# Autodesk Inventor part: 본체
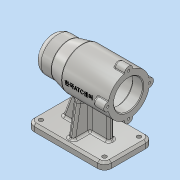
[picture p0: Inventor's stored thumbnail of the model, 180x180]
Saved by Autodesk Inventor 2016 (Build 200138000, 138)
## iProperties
Created: 2019-07
Part Number: 본체
Material: 알루미늄 6061
Document SubType Name: Modeling
Designer: Administrator
Mass: 644.223 g
Surface Area: 653.912 cm^2
Volume: 238.601 cm^3
Density: 2.7 g/cm^3
Appearance: 알루미늄 - 평지
Author: Administrator
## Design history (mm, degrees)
sketch "스케치1"
  geometry: L1 (0, 0)-(30, 0); L2 (30, 0)-(30, 66.631); L3 (29.91, 67.358)-(25.09, 86.642); L4 (25, 87.369)-(25, 102); L5 (15, 112)-(0, 112); L6 (0, 112)-(0, 0); L7 (21, 0)-(21, 15); L8 (21, 15)-(21, 15); L9 (24, 18)-(24, 66); L10 (21, 69)-(21, 69); L11 (21, 69)-(21, 80.7); L12 (20.7, 81)-(17.5, 81); L13 (17.5, 81)-(17.5, 98.7); L14 (17.2, 99)-(16, 99); L15 (16, 99)-(16, 102.7); L16 (15.7, 103)-(10.5, 103); L17 (10.5, 103)-(10.5, 103); L18 (7.5, 106)-(0, 106); A1 r 0.3 centre (15.7, 102.7) between (16, 102.7) and (15.7, 103); A2 r 0.3 centre (17.2, 98.7) between (17.5, 98.7) and (17.2, 99); A3 r 0.3 centre (20.7, 80.7) between (21, 80.7) and (20.7, 81); A4 r 10 centre (15, 102) between (25, 102) and (15, 112); A5 r 3 centre (28, 87.369) between (25, 87.369) and (25.09, 86.642); A6 r 3 centre (27, 66.631) between (30, 66.631) and (29.91, 67.358); A7 r 3 centre (21, 66) between (24, 66) and (21, 69); A8 r 3 centre (21, 18) between (21, 15) and (24, 18); A9 r 3 centre (7.5, 103) between (10.5, 103) and (7.5, 106); 3 further points
  constraints: 36 end point, 18 point on circle, 18 tangent, 14 perpendicular, 9 centre point, 8 point on line, 5 equal radius, 2 horizontal, 1 parallel
  dimensions: "d0" = 112 distance between parallel lines of L1 L5; "d1" = 60 diameter of L2 L6; "d2" = 50 diameter of L4 L6; "d3" = 25 distance of point (25, 87) point (25, 112); "d4" = 45 distance from line of point (30, 67) L5; "d5" = 42 diameter of L7 L6; "d6" = 48 diameter of L9 L6; "d7" = 42 diameter of L11 L6; "d8" = 35 diameter of L13 L6; "d9" = 32 diameter of L15 L6; "d10" = 21 diameter of L17 L6; "d11" = 3 distance between parallel lines of L16 L18; "d12" = 4 distance between parallel lines of L14 L16; "d13" = 18 distance between parallel lines of L12 L14; "d14" = 12 distance between parallel lines of L10 L12; "d15" = 54 distance between parallel lines of L8 L10; "d16" = 15 distance between parallel lines of L1 L8; "d17" = 0.3 radius of A1; "d18" = 10 radius of A4; "d19" = 3 radius of A5; "d20" = 3 radius of A7
revolve "회전1" sketch "스케치1" stored, may be unused: angle "d21" = 90 deg
node "작업 평면1"
sketch "스케치2"
  geometry: L1 (25, 112)-(-25, 112); L2 (-35, 102)-(-35, 10); L3 (-25, 0)-(25, 0); L4 (35, 10)-(35, 102); L5 (-30, 0)-(30, 0) reference; A1 r 10 centre (25, 102) between (35, 102) and (25, 112); A2 r 10 centre (-25, 102) between (-25, 112) and (-35, 102); A3 r 10 centre (-25, 10) between (-35, 10) and (-25, 0); A4 r 10 centre (25, 10) between (25, 0) and (35, 10); 1 further point
  constraints: 8 end point, 8 point on circle, 8 tangent, 4 centre point, 3 equal radius, 2 parallel, 1 collinear, 1 horizontal, 1 perpendicular
  dimensions: "d23" = 112 distance between parallel lines of L3 L1; "d24" = 70 distance between parallel lines of L2 L4; "d25" = 35 distance from line of point (0, 0) L4; "d26" = 10 radius of A1
extrude "돌출1" join sketch "스케치2" distance "d27" = 10; taper "d28" = 0 deg
hole "구멍1" diameter "d31" = 6; stored, may be unused: countersink angle "d35" = 90 deg, drill point angle "d37" = 118 deg; dims "d29" = 10, "d30" = 10, "d32" = 6, "d33" = 4, "d34" = 2, "d36" = 8
node "작업 평면2"
sketch "스케치3"
  geometry: L1 (-25, -70)-(-35, -70) reference; L2 (-28, -70)-(-21.176, -31.302); L3 (35, -70)-(25, -70) reference; L4 (28, -70)-(21.619, -33.809); L5 (-35, -80)-(-35, -70) reference; L6 (35, -80)-(35, -70) reference; 1 further point
  constraints: 4 end point, 2 point on line
  dimensions: "d45" = 7 distance from line of L2.start L5; "d46" = 7 distance from line of L6 L4.start; "d47" = 100 deg angle of L1 L2; "d48" = 100 deg angle of L3 L4
sketch "스케치4"
  geometry: L1 (-4, -60)-(4, -60); L2 (4, -60)-(4, -25); L3 (4, -25)-(-4, -25); L4 (-4, -25)-(-4, -60); L5 (-25, 0)-(25, 0) reference; 1 further point
  constraints: 8 end point, 2 parallel, 1 horizontal, 1 perpendicular
  dimensions: "d49" = 8 distance between parallel lines of L4 L2; "d50" = 4 distance from line of point (0, 0) L4; "d51" = 25 distance between parallel lines of L5 L3; "d52" = 60 distance between parallel lines of L5 L1
extrude "돌출2" join sketch "스케치4" stored distance "d53" = 10; taper "d54" = 0 deg
feature "리브1" dims "d55" = 1, "d56" = 8, "d57" = 0, "d58" = 0, "d59" = 1, "d60" = 1
feature "리브2" dims "d61" = 1, "d62" = 8, "d63" = 0, "d64" = 0, "d65" = 1, "d66" = 1
sketch "스케치5"
  geometry: L1 (-70, 10)-(-70, 102) reference; L2 (-70, 92)-(-43.589, 82.387); L3 (-80, 112)-(-70, 112) reference; 1 further point
  constraints: 2 end point, 1 point on line
  dimensions: "d67" = 20 distance from line of L2.start L3; "d68" = 110 deg angle of L2 L1
feature "리브3" sketch "스케치5" dims "d69" = 1, "d70" = 8, "d71" = 0, "d72" = 0, "d73" = 1, "d74" = 1
chamfer "모따기1" distance "d90" = 3; stored, may be unused: second distance "d91" = 2, angle "d92" = 45 deg
chamfer "모따기2" distance "d93" = 1; stored, may be unused: second distance "d94" = 2, angle "d95" = 45 deg
fillet "모깎기1" dims "d97" = 3
node "작업 평면3"
sketch "스케치7"
  geometry: L1 (30, -33.315)-(30, -33.315) reference; L2 (30, -33.315)-(30, -33.315) reference; 5 further points
  constraints: 1 point on line, 1 vertical alignment, 1 other
  dimensions: "d98" = 42 distance from line of L1 point (0, 8.685)
feature "엠보싱1" sketch "스케치7" dims "d0" = 112, "d1" = 60, "d2" = 50, "d3" = 25, "d4" = 45, "d5" = 42, "d6" = 48, "d7" = 42, "d8" = 35, "d9" = 32, "d10" = 21, "d11" = 3, "d12" = 4, "d13" = 18, "d14" = 12, "d15" = 54, "d16" = 15, "d17" = 0.3, "d18" = 10, "d19" = 3, "d20" = 3, "d99" = 0.5, "d100" = 0
sketch "스케치8" dims "d102" = 60
  geometry: C1 r 6 at (30, 0); C2 r 6 at (0, 30); C3 r 6 at (-30, 0); C4 r 6 at (0, -30); C5 r 30 at (0, 0) reference; 6 further points
  constraints: 4 centre point, 4 coincident, 1 horizontal alignment, 1 vertical alignment, 12 other
  dimensions: "d103" = 12 diameter of C1; "d106" = 360 deg dimension on point (0, 0) C1.centre (derived)
extrude "돌출4" join sketch "스케치8" distance "d108" = 16; taper "d109" = 0 deg
hole "구멍3" sketch "스케치8" diameter "d110" = 3.242; stored, may be unused: countersink angle "d114" = 90 deg, drill point angle "d116" = 118 deg; dims "d111" = 8, "d112" = 4, "d113" = 2, "d115" = 11
fillet "모깎기2" dims "d117" = 3, "d118" = 1
node "솔리드1"
pattern_linear "직사각형 패턴1" dims "d40" = 92
other parameters: "d44" = 56
